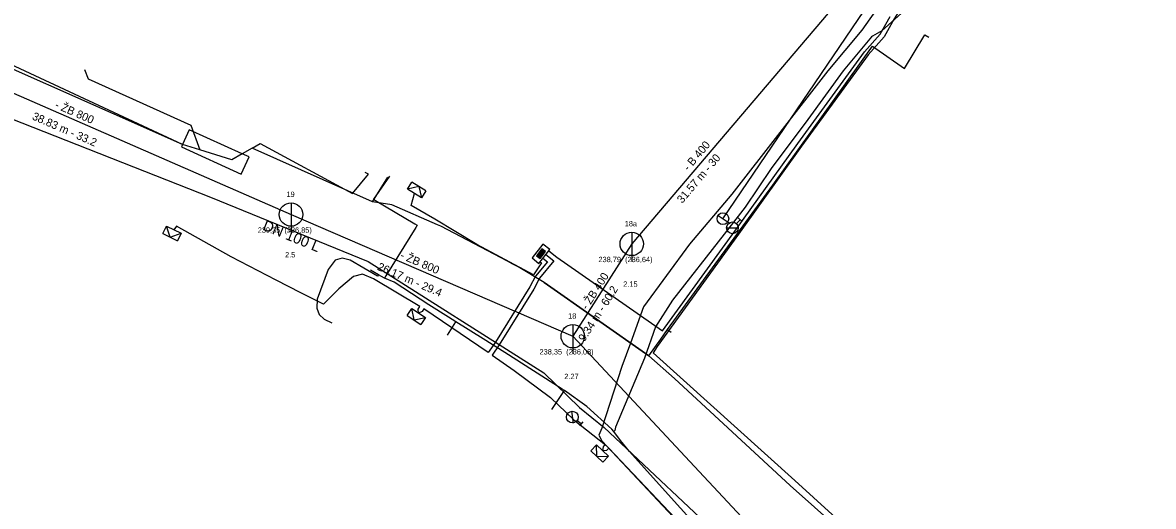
# Model space of a CAD drawing. Extents: x -600636 to -600148, y -1203980 to -1203569.
# Drawn here: x -600483.1 to -600386.7, y -1203876.3 to -1203835 of the extents above; entities that cross this region are included whole.
import ezdxf

# ---------------------------------------------------------------- set-up
doc = ezdxf.new("R2010")
doc.units = 0
for name, color, linetype in [('Cetin kolektor kabelovod', 7, 'Continuous'), ('Cetin nezaměřený', 7, 'Continuous'), ('Cetin NN přípojka', 7, 'Continuous'), ('Cetin zam průběh', 7, 'Continuous'), ('EON objekty', 7, 'Continuous'), ('EON podzemní NN', 7, 'Continuous'), ('EON podzemní VN', 7, 'Continuous'), ('GasNet STL', 7, 'Continuous'), ('Implicitní', 7, 'Continuous'), ('VaK Břeclav_kanalizace', 7, 'Continuous'), ('Vak Břeclav_vodovod', 7, 'Continuous'), ('Vrstva 9', 7, 'Continuous')]:
    doc.layers.add(name, color=color, linetype=linetype)

# ---------------------------------------------------------------- blocks, each defined once
blk = doc.blocks.new('NN630')
at = {"layer": 'Vrstva 9'}
for points in [[(-0.003, -0.7), (-0.703, 0)], [(-0.703, -0.7), (-0.703, 0), (0.697, 0), (0.697, -0.7)], [(-0.703, -0.7), (0.697, -0.7)], [(-0.003, -0.7), (0.697, 0)]]:
    blk.add_lwpolyline(points, dxfattribs=at)
blk = doc.blocks.new('NN620')
at = {"layer": 'EON objekty'}
for points in [[(0.752, 0.004), (-0.748, 0.004)], [(-0.748, 0.004), (-0.748, -0.746)], [(0.752, -0.746), (0.752, 0.004)], [(-0.748, -0.746), (0.752, -0.746)], [(0.368, -0.18), (-0.376, -0.18)], [(-0.376, -0.18), (-0.376, -0.558)], [(-0.376, -0.558), (0.368, -0.558)], [(0.321, -0.227), (-0.329, -0.227)], [(-0.329, -0.227), (-0.329, -0.51)], [(-0.329, -0.51), (0.321, -0.51)], [(0.274, -0.274), (-0.281, -0.274)], [(-0.281, -0.274), (-0.281, -0.463)], [(-0.281, -0.463), (0.274, -0.463)], [(0.227, -0.321), (-0.234, -0.321)], [(-0.234, -0.321), (-0.234, -0.416)], [(-0.234, -0.416), (0.227, -0.416)], [(-0.193, -0.369), (0.185, -0.369)], [(0.227, -0.416), (0.227, -0.321)], [(0.274, -0.463), (0.274, -0.274)], [(0.321, -0.51), (0.321, -0.227)], [(0.368, -0.558), (0.368, -0.18)]]:
    blk.add_lwpolyline(points, dxfattribs=at)
blk = doc.blocks.new('MoSymbol 2')
at = {"layer": 'Implicitní'}
blk.add_line((0, 0.0005), (0, -0.00075), dxfattribs=at)
blk.add_circle((0, 0), 0.0005, dxfattribs=at)
blk = doc.blocks.new('MoSymbol 3')
at = {"layer": 'Implicitní'}
for p, q in [((-0.000365, -0.000365), (0.000365, 0.000365)), ((-0.000225, 0.00095), (0.000225, 0.00095)), ((0, 0.00095), (0, 0.0005))]:
    blk.add_line(p, q, dxfattribs=at)
blk.add_circle((0, 0), 0.0005, dxfattribs=at)

msp = doc.modelspace()

# ---------------------------------------------------------------- linework, layer by layer
at = {"layer": 'Cetin kolektor kabelovod'}
msp.add_lwpolyline([(-600469.44, -1203845.43), (-600488.73, -1203836.43)], dxfattribs=at)
msp.add_lwpolyline([(-600468.86, -1203844.17), (-600469.44, -1203845.43), (-600469.53, -1203845.63), (-600464.42, -1203847.94), (-600463.76, -1203846.48), (-600464.35, -1203846.21), (-600468.86, -1203844.17)], close=True, dxfattribs=at)
at = {"layer": 'Cetin nezaměřený'}
for points in [[(-600467.951, -1203845.887), (-600469.44, -1203845.43), (-600492.51, -1203835.18)], [(-600464.35, -1203846.21), (-600465.24, -1203846.72), (-600467.951, -1203845.887)]]:
    msp.add_lwpolyline(points, dxfattribs=at)
at = {"layer": 'Cetin NN přípojka'}
for points in [[(-600467.951, -1203845.887), (-600469.44, -1203845.43), (-600492.51, -1203835.18)], [(-600464.35, -1203846.21), (-600465.24, -1203846.72), (-600467.951, -1203845.887)], [(-600463.5, -1203845.73), (-600464.35, -1203846.21)], [(-600453.22, -1203850.31), (-600463.5, -1203845.73)], [(-600451.58, -1203850.57), (-600453.22, -1203850.31)], [(-600447.41, -1203852.39), (-600447.68, -1203852.27), (-600451.58, -1203850.57)], [(-600441.73, -1203855.36), (-600447.41, -1203852.39)], [(-600441.27, -1203855.62), (-600441.73, -1203855.36)], [(-600440.81, -1203855.85), (-600441.27, -1203855.62)], [(-600429.66, -1203863.46), (-600438.6, -1203857.18), (-600440.81, -1203855.85)], [(-600427.47, -1203865.39), (-600429.66, -1203863.46)], [(-600401.59, -1203888.87), (-600406.17, -1203884.71), (-600411.15, -1203880.27), (-600417.62, -1203874.52), (-600427.47, -1203865.39)]]:
    msp.add_lwpolyline(points, dxfattribs=at)
at = {"layer": 'Cetin zam průběh'}
for points in [[(-600428.66, -1203862.04), (-600428.08, -1203861.21), (-600419.11, -1203848.88), (-600410.59, -1203837.02), (-600407.88, -1203838.93), (-600406.15, -1203836.06)], [(-600406.15, -1203836.06), (-600405.81, -1203836.27)], [(-600477.78, -1203839.031), (-600477.466, -1203839.807), (-600468.712, -1203843.784), (-600467.951, -1203845.887)], [(-600463.5, -1203845.73), (-600462.8, -1203845.332), (-600454.941, -1203849.599), (-600453.58, -1203847.939), (-600453.845, -1203847.799)], [(-600463.5, -1203845.73), (-600464.35, -1203846.21)], [(-600453.22, -1203850.31), (-600463.5, -1203845.73)], [(-600453.22, -1203850.31), (-600451.93, -1203848.2)], [(-600451.58, -1203850.57), (-600453.22, -1203850.31)], [(-600447.41, -1203852.39), (-600447.68, -1203852.27), (-600451.58, -1203850.57)], [(-600441.73, -1203855.36), (-600447.41, -1203852.39)], [(-600441.27, -1203855.62), (-600441.73, -1203855.36)], [(-600440.81, -1203855.85), (-600441.27, -1203855.62)], [(-600429.66, -1203863.46), (-600438.6, -1203857.18), (-600440.81, -1203855.85)], [(-600438.6, -1203857.18), (-600429.66, -1203863.46)], [(-600428.08, -1203861.21), (-600427.76, -1203861.43)], [(-600429.66, -1203863.46), (-600428.66, -1203862.04)], [(-600427.47, -1203865.39), (-600429.66, -1203863.46)], [(-600401.59, -1203888.87), (-600406.17, -1203884.71), (-600411.15, -1203880.27), (-600417.62, -1203874.52), (-600427.47, -1203865.39)]]:
    msp.add_lwpolyline(points, dxfattribs=at)
at = {"layer": 'EON podzemní NN'}
for points in [[(-600401.18, -1203821.86), (-600400.885, -1203822.127), (-600402.931, -1203825.356), (-600408.748, -1203834.692), (-600409.616, -1203836.226), (-600410.963, -1203837.774), (-600416.658, -1203845.568), (-600422.028, -1203853.057), (-600428.974, -1203862.664), (-600429.3, -1203863.19), (-600417.22, -1203874.08), (-600405.45, -1203884.79), (-600399.15, -1203890.52), (-600398.44, -1203891.61), (-600393.326, -1203896.191), (-600393.457, -1203899.76), (-600393.232, -1203899.82)], [(-600428.496, -1203861.319), (-600422.353, -1203852.823), (-600416.981, -1203845.332), (-600411.277, -1203837.525), (-600409.944, -1203835.994), (-600409.092, -1203834.488)], [(-600438.946, -1203855.441), (-600438.834, -1203855.528), (-600439.513, -1203856.54), (-600444.33, -1203853.94), (-600447.92, -1203851.79), (-600449.93, -1203850.62), (-600449.655, -1203849.593)], [(-600438.7, -1203855.126), (-600438.312, -1203855.428), (-600439.338, -1203856.638), (-600439.814, -1203857.561), (-600442.757, -1203862.28), (-600443.365, -1203863.167), (-600448.864, -1203859.443), (-600448.985, -1203859.656), (-600449.299, -1203859.803), (-600449.333, -1203859.458), (-600449.202, -1203859.228), (-600453.16, -1203856.89), (-600454.08, -1203856.47), (-600454.84, -1203856.67), (-600456.112, -1203857.726), (-600457.402, -1203859.03), (-600459.35, -1203858.06), (-600461.46, -1203856.98), (-600465.28, -1203854.99), (-600469.95, -1203852.39), (-600470.174, -1203852.686)], [(-600438.454, -1203854.81), (-600437.764, -1203855.351), (-600438.982, -1203856.822), (-600439.466, -1203857.759), (-600442.423, -1203862.5), (-600443.035, -1203863.393), (-600441.16, -1203864.7), (-600438.07, -1203867), (-600436.07, -1203868.9), (-600433.379, -1203871.043), (-600433.572, -1203871.222), (-600433.619, -1203871.529), (-600433.266, -1203871.492), (-600433.082, -1203871.316), (-600424.84, -1203880.03), (-600423.538, -1203881.525), (-600424.029, -1203882.002), (-600424.137, -1203882.385)], [(-600438.208, -1203854.495), (-600437.523, -1203855.028), (-600428.496, -1203861.319)]]:
    msp.add_lwpolyline(points, dxfattribs=at)
at = {"layer": 'EON podzemní VN'}
msp.add_lwpolyline([(-600408.835, -1203831.858), (-600411.506, -1203835.68), (-600414.412, -1203839.145), (-600422.594, -1203849.646), (-600426.194, -1203853.932), (-600430.114, -1203859.273), (-600431.226, -1203862.375), (-600431.964, -1203864.361), (-600433.679, -1203869.626), (-600433.941, -1203870.22), (-600433.675, -1203870.696), (-600426.744, -1203878.086), (-600409.663, -1203896.312), (-600402.458, -1203904.238), (-600401.465, -1203905.565), (-600402.307, -1203907.459), (-600406.208, -1203910.525), (-600416.956, -1203919.847)], dxfattribs=at)
at = {"layer": 'GasNet STL'}
for points in [[(-600408.12, -1203834.21), (-600409.81, -1203835.72), (-600410.59, -1203836.18), (-600410.69, -1203836.24), (-600410.982, -1203836.59), (-600413.1, -1203839.13), (-600416.12, -1203843.3), (-600419.23, -1203847.46), (-600421.46, -1203850.76), (-600423.251, -1203853.057), (-600427.65, -1203858.7), (-600429.09, -1203860.98), (-600430.04, -1203863.64), (-600432.51, -1203869.52), (-600432.57, -1203869.82), (-600432.66, -1203869.91), (-600432.82, -1203869.71), (-600434.95, -1203867.78), (-600436.87, -1203866.4), (-600437.06, -1203866.29), (-600441.96, -1203863.17), (-600443.79, -1203862.01), (-600446.12, -1203860.55), (-600446.75, -1203860.15), (-600448.44, -1203859.11), (-600451.4, -1203857.16), (-600452.21, -1203856.82), (-600452.72, -1203856.53), (-600453.39, -1203856.149)], [(-600451.79, -1203848.11), (-600453.15, -1203850.09), (-600452.98, -1203850.192), (-600449.624, -1203852.197), (-600449.429, -1203852.313), (-600449.536, -1203852.486), (-600452.096, -1203856.635), (-600452.21, -1203856.82)], [(-600452.72, -1203856.53), (-600452.8, -1203856.64), (-600455.14, -1203855.28), (-600455.81, -1203855.12), (-600456.42, -1203855.28), (-600457.01, -1203856.09), (-600457.95, -1203858.62), (-600457.99, -1203859.39), (-600457.78, -1203859.91), (-600457.36, -1203860.33), (-600456.7, -1203860.63)], [(-600446.84, -1203861.68), (-600446.12, -1203860.55)], [(-600437.93, -1203868.02), (-600436.87, -1203866.4)], [(-600386.652, -1203923.85), (-600387.74, -1203922.51), (-600393.27, -1203915.72), (-600394.06, -1203914.88), (-600396.47, -1203912.28), (-600396.484, -1203912.264), (-600401.03, -1203906.96), (-600401.08, -1203906.85), (-600401.1, -1203906.75), (-600400.76, -1203904.37), (-600400.74, -1203904.28), (-600400.82, -1203904.16), (-600403.82, -1203900.09), (-600410.79, -1203892.81), (-600417.35, -1203886.31), (-600422.32, -1203881.45), (-600423.18, -1203880.61), (-600423.976, -1203879.737), (-600427.52, -1203875.85), (-600431.32, -1203871.6), (-600432.09, -1203870.68), (-600432.66, -1203869.91)]]:
    msp.add_lwpolyline(points, dxfattribs=at)
at = {"layer": 'VaK Břeclav_kanalizace'}
for p, q in [((-600410.685, -1203829.843), (-600431.13, -1203853.9)), ((-600495.75, -1203835.832), (-600460.179, -1203851.393)), ((-600460.179, -1203851.393), (-600436.153, -1203861.776)), ((-600431.13, -1203853.9), (-600436.153, -1203861.776)), ((-600436.153, -1203861.776), (-600399.213, -1203901.336))]:
    msp.add_line(p, q, dxfattribs=at)
at = {"layer": 'Vak Břeclav_vodovod'}
for points in [[(-600423.358, -1203851.751), (-600404.489, -1203823.911), (-600397.059, -1203806.587), (-600395.742, -1203804.116)], [(-600485.045, -1203842.841), (-600467.036, -1203849.899), (-600453.613, -1203855.401), (-600438.627, -1203864.89), (-600435.585, -1203867.866)], [(-600435.585, -1203867.866), (-600433.489, -1203869.554), (-600422.424, -1203879.956), (-600409.57, -1203893.38), (-600398.755, -1203905.752)]]:
    msp.add_lwpolyline(points, dxfattribs=at)

# ---------------------------------------------------------------- block references
at = {"layer": 'EON podzemní NN'}
for name, p, rotation in [('NN630', (-600449.655, -1203849.592), 147.62218886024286), ('NN630', (-600470.174, -1203852.687), -26.373124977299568), ('NN620', (-600438.578, -1203854.967), -127.94031388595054), ('NN630', (-600449.299, -1203859.803), -33.67943898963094), ('NN630', (-600433.619, -1203871.529), -43.036452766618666)]:
    msp.add_blockref(name, p, dxfattribs=dict(at, rotation=rotation))
at = {"layer": 'VaK Břeclav_kanalizace', "xscale": 1999.750031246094, "yscale": 1999.750031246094}
for p in [(-600460.179, -1203851.393), (-600431.13, -1203853.9), (-600436.153, -1203861.776)]:
    msp.add_blockref('MoSymbol 2', p, dxfattribs=at)
at = {"layer": 'Vak Břeclav_vodovod', "xscale": 999.8750156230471}
for name, p, yscale, rotation in [('MoSymbol 2', (-600423.358, -1203851.751), 999.875015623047, 55.871659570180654), ('MoSymbol 3', (-600422.543, -1203852.53), 999.8750156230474, -43.65884022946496), ('MoSymbol 3', (-600436.197, -1203868.673), 999.8750156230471, -127.19116642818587)]:
    msp.add_blockref(name, p, dxfattribs=dict(at, yscale=yscale, rotation=rotation))

# ---------------------------------------------------------------- texts
at = {"layer": 'VaK Břeclav_kanalizace'}
for s, height, rotation, p in [('- ŽB 800', 0.6824, 336.37219, (-600480.374, -1203842.276)), ('38.83 m - 33.2', 0.68241, 336.37219, (-600482.315, -1203843.254)), ('- B 400', 0.6824, 49.64024, (-600426.294, -1203847.724)), ('31.57 m - 30', 0.68241, 49.64024, (-600426.826, -1203850.487)), ('- ŽB 800', 0.6824, 336.62736, (-600450.93, -1203855.108)), ('26.17 m - 29.4', 0.68241, 336.62736, (-600452.886, -1203856.089)), ('- ŽB 400', 0.6824, 57.47293, (-600434.933, -1203859.58)), ('9.34 m - 60.2', 0.68241, 57.47293, (-600435.161, -1203862.29))]:
    msp.add_text(s, height=height, rotation=rotation, dxfattribs=at).set_placement(p)
for s, height, p in [('19', 0.4549, (-600460.569, -1203849.893)), ('18a', 0.4549, (-600431.726, -1203852.4)), ('239,35  (236,85)', 0.45494, (-600463.017, -1203852.948)), ('2.5', 0.4549, (-600460.688, -1203855.048)), ('238,79  (236,64)', 0.45494, (-600433.968, -1203855.455)), ('2.15', 0.4549, (-600431.856, -1203857.555)), ('18', 0.4549, (-600436.554, -1203860.276)), ('238,35  (236,08)', 0.45494, (-600438.991, -1203863.331)), ('2.27', 0.4549, (-600436.879, -1203865.431))]:
    msp.add_text(s, height=height, dxfattribs=at).set_placement(p)
at = {"layer": 'Vak Břeclav_vodovod'}
msp.add_text('DN 100 L', height=0.9099, rotation=337.7116, dxfattribs=at).set_placement((-600462.671, -1203852.672))

doc.saveas('drawing.dxf')
